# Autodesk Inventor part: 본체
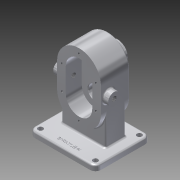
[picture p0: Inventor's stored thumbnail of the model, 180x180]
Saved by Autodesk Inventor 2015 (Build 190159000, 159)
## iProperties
Created: 2020-09
Part Number: 본체
Material: 알루미늄 6061
Document SubType Name: Modeling
Designer: LINEART-SSD.D4.16.05
Density: 2.7 g/cm^3
Appearance: 알루미늄 - 평지
Mass: 1440.46 g
Surface Area: 785.636 cm^2
Volume: 533.505 cm^3
Author: LINEART-SSD.D4.16.05
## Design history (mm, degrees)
sketch "스케치1"
  geometry: L1 (0, 62)-(0, -62); L2 (-40, 22)-(-40, -22); L3 (40, -22)-(40, 22); L4 (0, 46)-(0, -46); L5 (0, 46)-(0, -46); L6 (-24, 22)-(-24, -22); L7 (24, -22)-(24, 22); A1 r 40 centre (0, 22) between (40, 22) and (-40, 22); A2 r 40 centre (0, -22) between (-40, -22) and (40, -22); A3 r 24 centre (0, 22) between (24, 22) and (-24, 22); A4 r 24 centre (0, -22) between (-24, -22) and (24, -22); 6 further points
  constraints: 18 end point, 12 point on circle, 8 tangent, 6 point on line, 4 centre point, 4 coincident, 4 midpoint, 2 parallel, 1 collinear, 1 concentric, 1 vertical
  dimensions: "d1" = 124 distance of L1.start L1.end; "d2" = 40 radius of A1; "d3" = 92 distance of L4.start L4.end; "d4" = 48 diameter of A4; "d5" = 40 distance from line of point (0, 0) L3
extrude "돌출1" new body sketch "스케치1" distance "d6" = 53; taper "d7" = 0 deg
extrude "돌출2" cut sketch "스케치1" distance "d8" = 29; taper "d9" = 0 deg
sketch "스케치2"
  geometry: C1 r 12.5 at (0, 22); C2 r 12.5 at (0, -22); C3 r 8.5 at (0, 22); A1 r 24 centre (0, 22) between (24, 22) and (-24, 22) reference; A2 r 24 centre (0, -22) between (-24, -22) and (24, -22) reference; 1 further point
  constraints: 3 centre point, 3 coincident
  dimensions: "d10" = 25 diameter of C1; "d11" = 25 diameter of C2; "d12" = 17 diameter of C3
extrude "돌출3" cut sketch "스케치2" distance "d13" = 15; taper "d14" = 0 deg
node "작업 평면1"
extrude "돌출5" cut sketch "스케치2" distance "d20" = 35; taper "d21" = 0 deg
node "작업 평면2"
sketch "스케치4"
  geometry: L1 (-40, 0)-(-40, 53) reference; L2 (-19, 70)-(19, 70) reference; L3 (40, 0)-(-40, 0) reference; L4 (0, -30)-(-50, -30); L5 (0, -30)-(50, -30); L6 (60, -20)-(60, 60); L7 (50, 70)-(0, 70); L8 (0, 70)-(-50, 70); L9 (-60, 60)-(-60, -20); C1 r 4.5 at (-50, -20); C2 r 4.5 at (50, -20); C3 r 4.5 at (50, 60); C4 r 4.5 at (-50, 60); A1 r 10 centre (-50, -20) between (-60, -20) and (-50, -30); A2 r 10 centre (-50, 60) between (-50, 70) and (-60, 60); A3 r 10 centre (50, 60) between (60, 60) and (50, 70); A4 r 10 centre (50, -20) between (50, -30) and (60, -20); 4 further points
  constraints: 12 end point, 11 tangent, 8 centre point, 8 point on circle, 7 point on line, 4 coincident, 3 equal radius, 3 perpendicular, 1 midpoint
  dimensions: "d23" = 100 distance of L7.end L4.start; "d24" = 60 distance of L4.start point (-60, -30); "d25" = 60 distance of L4.start point (60, -30); "d26" = 10 radius of A1; "d27" = 9 diameter of C1; "d28" = 9 diameter of C2; "d29" = 9 diameter of C3; "d30" = 9 diameter of C4
extrude "돌출6" join sketch "스케치4" distance "d31" = 10; taper "d32" = 0 deg
fillet "모깎기1" dims "d33" = 3
sketch "스케치5"
  geometry: L1 (40, 0)-(40, -53) reference; L2 (-40, 0)-(-40, -53) reference; L3 (-60, 20)-(-60, -60) reference; L4 (-50, -70)-(50, -70) reference; L5 (-40, -45)-(40, -45); L6 (40, -45)-(40, -8); L7 (40, -8)-(-40, -8); L8 (-40, -8)-(-40, -45); 1 further point
  constraints: 8 end point, 4 point on line, 2 perpendicular
  dimensions: "d35" = 37 distance of L5.end L6.end; "d36" = 25 distance between parallel lines of L4 L5
extrude "돌출7" join sketch "스케치5" stored distance "d37" = 10; taper "d38" = 0 deg
fillet "모깎기2" dims "d39" = 3
fillet "모깎기3" dims "d40" = 3
fillet "모깎기4" dims "d41" = 3
sketch "스케치6"
  geometry: C1 r 8.5 at (0, 22) reference; C2 r 19 at (0, 22); C3 r 14 at (0, 22); 1 further point
  constraints: 2 centre point, 2 coincident
  dimensions: "d43" = 38 diameter of C2; "d44" = 28 diameter of C3
extrude "돌출8" join sketch "스케치6" distance "d45" = 17; taper "d46" = 0 deg
extrude "돌출9" cut sketch "스케치6" distance "d47" = 17; taper "d48" = 0 deg
sketch "스케치7"
  geometry: L1 (41, 70)-(3, 70) reference; L2 (3, 53)-(41, 53) reference; L3 (22, 69.3)-(22, 53); L4 (22, 70)-(36, 70); L5 (36, 69.3)-(36, 63.2); L6 (35.5, 62.7)-(22, 62.7); L7 (36, 69.3)-(36.404, 70); L8 (36, 69.3)-(37.743, 69.3); L9 (22, 69.3)-(22, 70); A1 r 0.5 centre (35.5, 63.2) between (35.5, 62.7) and (36, 63.2); 2 further points
  constraints: 14 end point, 5 point on line, 2 midpoint, 2 perpendicular, 2 point on circle, 2 tangent, 1 centre point, 1 horizontal, 1 vertical
  dimensions: "d49" = 14 distance of L4.start L4.end; "d50" = 7.3 distance of L4.end point (36, 62.7); "d52" = 60 deg angle of L8 L7; "d53" = 0.5 radius of A1; "d54" = 0.7 distance between parallel lines of L8 L1; "d55" = 14 distance between parallel lines of L5 L9; "d56" = 0.7 distance from line of L3.start L1; "d57" = 1.50953 distance from line of L8.end L7
revolve "회전1" sketch "스케치7" stored, may be unused: angle "d58" = 90 deg
chamfer "모따기1" distance "d59" = 1; stored, may be unused: second distance "d60" = 2, angle "d61" = 45 deg
sketch "스케치8"
  geometry: L1 (24, 22)-(24, -22) reference; L2 (-24, -22)-(-24, 22) reference; L3 (40, 22)-(40, -22) reference; L4 (-40, -22)-(-40, 22) reference; L5 (0, 53)-(0, -53); L6 (-31, 22)-(-31, -22); L7 (31, -22)-(31, 22); L8 (0, 0)-(0, 53); L9 (-31, 22)-(31, 22); L10 (-31, -22)-(31, -22); L11 (0, 0)-(0, -53); A1 r 24 centre (0, 22) between (24, 22) and (-24, 22) reference; A2 r 24 centre (0, -22) between (-24, -22) and (24, -22) reference; A3 r 40 centre (0, 22) between (40, 22) and (-40, 22) reference; A4 r 40 centre (0, -22) between (-40, -22) and (40, -22) reference; A5 r 31 centre (0, 22) between (31, 22) and (-31, 22); A6 r 31 centre (0, -22) between (-31, -22) and (31, -22); 1 further point
  constraints: 16 end point, 6 point on circle, 4 tangent, 2 centre point, 2 parallel, 2 perpendicular, 2 point on line, 1 coincident, 1 collinear, 1 midpoint, 1 vertical
  dimensions: "d62" = 106 distance of L5.start L5.end; "d63" = 62 diameter of A6; "d64" = 9 distance between parallel lines of L3 L7
hole "구멍1" sketch "스케치8" at (0, 53), (-31, 22), (31, 22), (31, -22), (-31, -22), (0, -53) diameter "d65" = 4.134; stored, may be unused: countersink angle "d69" = 90 deg, drill point angle "d71" = 118 deg; dims "d66" = 10, "d67" = 4, "d68" = 2, "d70" = 12
fillet "모깎기6" dims "d72" = 3
fillet "모깎기7" dims "d73" = 3
node "작업 평면3"
sketch "스케치9"
  geometry: L1 (40, -77)-(40, -22) reference; L2 (40, -22)-(40, 22) reference; L3 (-40, 22)-(-40, -22) reference; L4 (-40, -22)-(-40, -77) reference; L5 (50, 0)-(-50, 0); L6 (50, 0)-(50, 11); L7 (50, 11)-(37.187, 11); L8 (37.187, 11)-(37.187, 0); L9 (-50, 0)-(-50, 11); L10 (-50, 11)-(-38.161, 11); L11 (-38.161, 11)-(-38.161, 0); 2 further points
  constraints: 14 end point, 4 point on line, 3 perpendicular, 2 midpoint, 1 coincident, 1 horizontal, 1 vertical
  dimensions: "d75" = 100 distance of L5.start L5.end; "d76" = 11 distance of L5.start L6.end; "d77" = 11 distance of L5.end L9.end; "d78" = 2.81266 distance between parallel lines of L1 L8; "d79" = 78.1613 distance between parallel lines of L1 L11
revolve "회전2" sketch "스케치9" stored, may be unused: angle "d80" = 90 deg
fillet "모깎기8" dims "d81" = 3
sketch "스케치10"
  geometry: C1 r 11 at (0, 0) reference; 1 further point
hole "구멍2" sketch "스케치10" at (0, 0) diameter "d82" = 8.376; stored, may be unused: countersink angle "d86" = 90 deg, drill point angle "d88" = 118 deg; dims "d83" = 20, "d84" = 4, "d85" = 2, "d87" = 27.3
sketch "스케치11"
  geometry: L1 (60, -60)-(60, 20) reference; L2 (50, 30)-(-50, 30) reference; 2 further points
  constraints: 1 other
  dimensions: "d89" = 60 distance from line of L1 point (0, 18); "d90" = 12 distance from line of L2 point (0, 18)
feature "엠보싱1" sketch "스케치11" dims "d91" = 0.5, "d92" = 0
node "솔리드1"
node "투영된 루프1"
node "투영된 루프2"
other parameters: "d74" = 14
